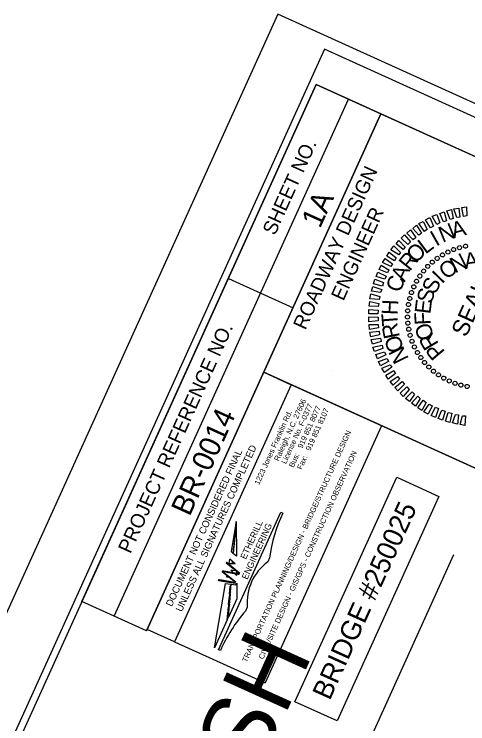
# Model space of a CAD drawing. Extents: x 1744741 to 2014229, y 466994 to 951338.
# Drawn here: x 2010827 to 2011187, y 477413 to 477976 of the extents above; entities that cross this region are included whole.
import ezdxf

# ---------------------------------------------------------------- set-up
doc = ezdxf.new("R2010")
doc.units = 0
for name, color, linetype in [('Old_Level_1', 7, 'Continuous'), ('Old_Level_30', 7, 'Continuous'), ('Old_Level_31', 7, 'Continuous'), ('Old_Level_34', 7, 'Continuous'), ('Old_Level_49', 7, 'Continuous'), ('Old_Level_50', 7, 'Continuous'), ('Prop Guardrail', 7, 'Continuous'), ('Sheet Data Field CELL', 7, 'Continuous'), ('Sheet Plan CELL', 7, 'Continuous'), ('Sheet Plot Border Inside CELL', 7, 'Continuous'), ('Sheet Plot Border Outside CELL', 7, 'Continuous'), ('Sheet Sticker Exception Certification CELL', 7, 'Continuous'), ('Sheet Sticker Preliminary CELL', 7, 'Continuous')]:
    doc.layers.add(name, color=color, linetype=linetype)

msp = doc.modelspace()

# ---------------------------------------------------------------- linework, layer by layer
at = {"layer": 'Old_Level_1'}
msp.add_line((2010603.58, 476285.44), (2011175.48, 477547.17), dxfattribs=at)
at = {"layer": 'Old_Level_30'}
for p, q in [((2011046.61, 477681.87), (2010954.24, 477478.1)), ((2011118.33, 477649.36), (2011046.61, 477681.87)), ((2011118.33, 477649.36), (2011025.97, 477445.59)), ((2010954.24, 477478.1), (2011025.97, 477445.59))]:
    msp.add_line(p, q, dxfattribs=at)
at = {"layer": 'Old_Level_34'}
msp.add_lwpolyline([(2011049.62, 477430.54), (2011130.29, 477608.53), (2011163.83, 477593.33), (2011083.15, 477415.34)], close=True, dxfattribs=at)
at = {"layer": 'Old_Level_49'}
for p, q in [((2010988.95, 477471.76), (2011038.41, 477580.88)), ((2011038.41, 477580.88), (2011039.97, 477580.17)), ((2011003.08, 477573.41), (2010999, 477549.69)), ((2011002.64, 477567.97), (2011002.84, 477570.47)), ((2011002.84, 477570.81), (2011002.8, 477570.38)), ((2011002.8, 477570.38), (2011002.84, 477570.47)), ((2011002.88, 477570.88), (2011002.84, 477570.81)), ((2011002.88, 477570.88), (2011003, 477572.41)), ((2011003, 477572.53), (2011003.08, 477573.41)), ((2011003.01, 477572.56), (2011003.08, 477573.41)), ((2011003.08, 477573.41), (2011003.27, 477545.97)), ((2011002.18, 477563.56), (2011002.1, 477562.74)), ((2011002.31, 477563.85), (2011002.18, 477563.56)), ((2011002.31, 477563.85), (2011002.59, 477567.28)), ((2011002.57, 477567.8), (2011002.5, 477567.09)), ((2011002.5, 477567.09), (2011002.59, 477567.28)), ((2011002.64, 477567.97), (2011002.57, 477567.8)), ((2011001.64, 477555.58), (2011002.25, 477563.06)), ((2011002.1, 477562.74), (2011002.25, 477563.06)), ((2011000.76, 477548.16), (2011001.29, 477553.9)), ((2011001.02, 477547.93), (2011001.55, 477554.48)), ((2011001.39, 477555.04), (2011001.29, 477553.9)), ((2011001.29, 477553.9), (2011001.55, 477554.48)), ((2011001.64, 477555.58), (2011001.39, 477555.04)), ((2010999, 477549.69), (2011000.76, 477548.16)), ((2011003.27, 477545.97), (2011001.02, 477547.93)), ((2011000.17, 477541.75), (2010997.95, 477543.59)), ((2011000.02, 477540.11), (2011000.17, 477541.75)), ((2011000.5, 477541.47), (2011000.39, 477540.09)), ((2011002.27, 477540), (2011000.5, 477541.47)), ((2011029.46, 477544.54), (2011028.04, 477541.42)), ((2010997.38, 477540.23), (2011000.02, 477540.11)), ((2011000.39, 477540.09), (2011002.27, 477540)), ((2010995.5, 477529.33), (2010995.76, 477530.83)), ((2010995.76, 477530.83), (2010997.55, 477528.95)), ((2010998.84, 477534.95), (2010999.54, 477534.89)), ((2010999.49, 477534.32), (2010998.84, 477534.95)), ((2010999.54, 477534.89), (2010999.49, 477534.32)), ((2011003.37, 477530.55), (2010999.89, 477533.93)), ((2010999.97, 477534.85), (2011003.35, 477534.55)), ((2011003.35, 477534.55), (2011003.37, 477530.55)), ((2010985.84, 477473.17), (2010994.63, 477524.29)), ((2010994.63, 477524.29), (2010999.07, 477523.72)), ((2010997.55, 477528.95), (2010995.5, 477529.33)), ((2011002.79, 477523.23), (2011003.42, 477524.59)), ((2011003.42, 477524.59), (2011003.5, 477512.14)), ((2010999.07, 477523.72), (2010998.37, 477522.17)), ((2010998.58, 477517.64), (2010999.07, 477523.72)), ((2010998.58, 477517.64), (2010999.07, 477523.72)), ((2010999.07, 477523.72), (2011002.79, 477523.23)), ((2010997.65, 477514.36), (2010998.46, 477516.14)), ((2010997.79, 477515.91), (2010997.65, 477514.36)), ((2010998.58, 477517.64), (2010997.79, 477515.91)), ((2010997.92, 477509.51), (2010998.46, 477516.14)), ((2010996.85, 477505.64), (2010997.77, 477507.67)), ((2010997.02, 477507.53), (2010996.85, 477505.64)), ((2011003.5, 477512.14), (2010996.97, 477497.72)), ((2010996.97, 477497.72), (2010997.77, 477507.67)), ((2010997.92, 477509.51), (2010997.02, 477507.53)), ((2011011.79, 477505.57), (2011010.38, 477502.45)), ((2010995.9, 477495.38), (2010985.84, 477473.17)), ((2010990.51, 477471.05), (2010988.95, 477471.76))]:
    msp.add_line(p, q, dxfattribs=at)
for centre, radius, start, end in [((2011147.4, 477529.1), 118.95, 154.5736, 172.5442), ((2011051.95, 477508.98), 40.3, 126.3806, 184.8539), ((2011103.21, 477421.73), 123.02, 138.9892, 156.3604)]:
    msp.add_arc(centre, radius, start, end, dxfattribs=at)
at = {"layer": 'Old_Level_50'}
for p, q in [((2011002.57, 477567.8), (2011002.8, 477570.38)), ((2011002.84, 477570.81), (2011002.99, 477572.38)), ((2011003, 477572.53), (2011002.99, 477572.38)), ((2011002.99, 477572.38), (2011003, 477572.41)), ((2011003.01, 477572.56), (2011003, 477572.53)), ((2011003.01, 477572.56), (2011003.08, 477573.41)), ((2011002.18, 477563.56), (2011002.5, 477567.09)), ((2011001.39, 477555.04), (2011002.1, 477562.74)), ((2011001.02, 477547.93), (2011000.76, 477548.16)), ((2010997.38, 477540.23), (2010997.95, 477543.59)), ((2011000.5, 477541.47), (2011000.17, 477541.75)), ((2011000.39, 477540.09), (2011000.02, 477540.11)), ((2010999.49, 477534.32), (2010999.89, 477533.93)), ((2010999.54, 477534.89), (2010999.97, 477534.85)), ((2010999.89, 477533.93), (2010999.97, 477534.85)), ((2010997.79, 477515.91), (2010998.37, 477522.17)), ((2010997.02, 477507.53), (2010997.65, 477514.36)), ((2010996.85, 477505.64), (2010997.77, 477507.67)), ((2010997.77, 477507.67), (2010996.85, 477505.64)), ((2010995.9, 477495.38), (2010996.85, 477505.64)), ((2010995.9, 477495.38), (2010996.97, 477497.72))]:
    msp.add_line(p, q, dxfattribs=at)
at = {"layer": 'Prop Guardrail'}
for p, q in [((2011175.44, 477789.07), (2011175.44, 477789.07)), ((2011180.11, 477790.66), (2011180.11, 477790.66)), ((2011184.8, 477791.75), (2011184.8, 477791.75)), ((2011166.59, 477784.81), (2011166.59, 477784.81)), ((2011170.88, 477787.19), (2011170.88, 477787.19)), ((2011158.55, 477779.07), (2011158.55, 477779.07)), ((2011162.41, 477782.13), (2011162.41, 477782.13)), ((2011151.67, 477772.06), (2011151.67, 477772.06)), ((2011154.85, 477775.8), (2011154.85, 477775.8)), ((2011148.65, 477768.12), (2011148.65, 477768.12)), ((2011146.04, 477763.99), (2011146.04, 477763.99)), ((2011141.95, 477754.97), (2011141.95, 477754.97)), ((2011143.79, 477759.57), (2011143.79, 477759.57)), ((2011140.57, 477750.29), (2011140.57, 477750.29)), ((2011139.59, 477745.42), (2011139.59, 477745.42)), ((2011138.87, 477740.56), (2011138.87, 477740.56)), ((2011138.86, 477735.62), (2011138.86, 477735.62)), ((2011139.1, 477730.7), (2011139.1, 477730.7)), ((2011139.84, 477725.79), (2011139.84, 477725.79)), ((2011140.88, 477721), (2011140.88, 477721)), ((2011142.47, 477716.32), (2011142.47, 477716.32)), ((2011144.35, 477711.76), (2011144.35, 477711.76)), ((2011146.63, 477707.52), (2011146.63, 477707.52)), ((2011149.41, 477703.3), (2011149.41, 477703.3)), ((2011152.37, 477699.48), (2011152.37, 477699.48)), ((2011079.26, 477692.97), (2011079.26, 477692.97)), ((2011155.68, 477695.88), (2011155.68, 477695.88)), ((2011159.38, 477692.6), (2011159.38, 477692.6)), ((2011163.47, 477689.63), (2011163.47, 477689.63)), ((2011167.5, 477687.07), (2011167.5, 477687.07)), ((2011171.91, 477684.82), (2011171.91, 477684.82)), ((2011176.51, 477682.98), (2011176.51, 477682.98)), ((2011181.3, 477681.55), (2011181.3, 477681.55)), ((2011186.02, 477680.52), (2011186.02, 477680.52))]:
    msp.add_line(p, q, dxfattribs=at)
for points in [[(2011183.31, 477815.15), (2011181.88, 477822.35), (2011185.63, 477822.99), (2011186.05, 477815.76)], [(2011162.15, 477808.81), (2011158.48, 477815.41), (2011162.05, 477816.76), (2011164.47, 477810.1)], [(2011167.31, 477810.92), (2011164.39, 477817.55), (2011167.96, 477818.9), (2011169.69, 477811.81)], [(2011172.67, 477812.93), (2011170.04, 477819.68), (2011173.73, 477820.73), (2011175.16, 477813.53)], [(2011178, 477814.35), (2011175.72, 477821.31), (2011179.68, 477821.86), (2011180.4, 477814.74)], [(2011152.29, 477803.4), (2011147.92, 477809.58), (2011151.18, 477811.31), (2011154.54, 477805.09)], [(2011157.06, 477806.3), (2011153.2, 477812.5), (2011156.5, 477814.33), (2011159.38, 477807.59)], [(2011147.77, 477800.51), (2011143.03, 477805.86), (2011146.11, 477808.3), (2011149.88, 477801.9)], [(2011139.19, 477793.03), (2011133.86, 477798.16), (2011136.44, 477800.58), (2011141.12, 477795.12)], [(2011143.38, 477796.81), (2011138.34, 477802.06), (2011141.22, 477804.59), (2011145.42, 477798.6)], [(2011135.46, 477789.16), (2011129.76, 477793.48), (2011132.02, 477796.28), (2011137.05, 477791.04)], [(2011132, 477784.8), (2011125.66, 477788.79), (2011128.06, 477791.9), (2011133.39, 477786.77)], [(2011128.61, 477780.04), (2011122.42, 477783.83), (2011124.36, 477787.03), (2011129.93, 477782.41)], [(2011125.56, 477775.49), (2011119.14, 477778.77), (2011121.08, 477781.97), (2011127.08, 477777.77)], [(2011123.03, 477770.46), (2011116.38, 477773.23), (2011117.91, 477776.61), (2011124.15, 477772.92)], [(2011120.8, 477765.54), (2011113.92, 477767.8), (2011115.45, 477771.18), (2011121.92, 477768)], [(2011119.1, 477760.14), (2011111.98, 477761.89), (2011113.1, 477765.45), (2011119.8, 477762.79)], [(2011117.48, 477754.95), (2011110.34, 477756.08), (2011111.46, 477759.65), (2011118.39, 477757.5)], [(2011116.48, 477749.47), (2011109.11, 477750.1), (2011109.87, 477753.95), (2011117.05, 477751.81)], [(2011115.69, 477743.9), (2011108.42, 477744.23), (2011109.04, 477747.78), (2011116.05, 477746.33)], [(2011115.3, 477738.15), (2011108.1, 477738.07), (2011108.22, 477741.6), (2011115.6, 477740.98)], [(2011115.51, 477732.62), (2011108.24, 477731.84), (2011108.25, 477735.66), (2011115.51, 477735.34)], [(2011115.97, 477727.1), (2011108.68, 477725.71), (2011108.48, 477729.63), (2011115.63, 477729.6)], [(2011116.64, 477721.48), (2011109.75, 477719.91), (2011108.91, 477723.5), (2011116.43, 477724.29)], [(2011117.95, 477716.2), (2011110.99, 477713.92), (2011110.19, 477717.61), (2011117.4, 477718.79)], [(2011119.42, 477710.71), (2011112.82, 477708.15), (2011111.48, 477711.72), (2011118.87, 477713.31)], [(2011121.57, 477705.66), (2011115.11, 477702.29), (2011113.76, 477705.87), (2011120.68, 477708.04)], [(2011123.89, 477700.41), (2011117.53, 477696.75), (2011115.89, 477700.21), (2011122.7, 477702.68)], [(2011126.44, 477695.67), (2011120.6, 477691.53), (2011118.41, 477694.87), (2011125.15, 477697.74)], [(2011129.39, 477690.75), (2011123.67, 477686.31), (2011121.68, 477689.55), (2011128.04, 477693.22)], [(2011132.58, 477686.34), (2011127.48, 477681.62), (2011125.05, 477684.44), (2011131.29, 477688.41)], [(2011136.41, 477682.26), (2011131.28, 477676.93), (2011128.86, 477679.76), (2011134.62, 477684.31)], [(2011140.24, 477678.18), (2011135.52, 477672.66), (2011133, 477675.28), (2011138.45, 477680.22)], [(2011144.51, 477674.51), (2011140.36, 477668.61), (2011137.2, 477670.91), (2011142.58, 477676.25)], [(2011148.87, 477671.05), (2011145.13, 477664.97), (2011141.97, 477667.27), (2011146.94, 477672.79)], [(2011153.62, 477667.91), (2011150.24, 477661.54), (2011146.94, 477663.53), (2011151.4, 477669.54)], [(2011158.36, 477665.27), (2011155.34, 477658.61), (2011151.95, 477660.4), (2011155.99, 477666.59)], [(2011163.48, 477662.95), (2011161.08, 477656.01), (2011157.59, 477657.59), (2011161.02, 477664.06)], [(2011168.7, 477660.83), (2011166.7, 477653.71), (2011163.13, 477655.08), (2011166.14, 477661.74)], [(2011173.94, 477659.32), (2011172.56, 477651.92), (2011168.89, 477653.09), (2011171.25, 477659.92)], [(2011179.32, 477658.12), (2011178.45, 477650.73), (2011174.64, 477651.59), (2011176.95, 477658.33)], [(2011184.8, 477657.12), (2011184.33, 477649.55), (2011180.73, 477650.32), (2011182.42, 477657.33)]]:
    msp.add_lwpolyline(points, close=True, dxfattribs=at)
for centre, major_axis in [((2011170.88, 477787.08), (-0.7, 1.46)), ((2011175.4, 477789.02), (-0.57, 1.52)), ((2011180.08, 477790.55), (-0.44, 1.56)), ((2011184.88, 477791.67), (-0.3, 1.59)), ((2011162.41, 477782.07), (-0.94, 1.32)), ((2011166.53, 477784.76), (-0.83, 1.39)), ((2011154.94, 477775.67), (-1.16, 1.13)), ((2011158.54, 477779.04), (-1.05, 1.23)), ((2011151.66, 477772.01), (-1.25, 1.03)), ((2011148.7, 477768.07), (-1.34, 0.91)), ((2011143.88, 477759.5), (-1.48, 0.67)), ((2011146.1, 477763.89), (-1.41, 0.79)), ((2011142.04, 477754.93), (-1.53, 0.54)), ((2011140.61, 477750.22), (-1.57, 0.4)), ((2011139.6, 477745.4), (-1.6, 0.26)), ((2011139.01, 477740.51), (-1.62, 0.12)), ((2011138.85, 477735.59), (-1.62, -0.02)), ((2011139.12, 477730.68), (-1.61, -0.16)), ((2011139.81, 477725.8), (-1.59, -0.3)), ((2011140.93, 477721.01), (-1.56, -0.44)), ((2011142.46, 477716.33), (-1.52, -0.57)), ((2011144.39, 477711.8), (-1.46, -0.7)), ((2011146.71, 477707.46), (-1.39, -0.83)), ((2011149.4, 477703.34), (-1.32, -0.94)), ((2011152.44, 477699.47), (-1.23, -1.05)), ((2011155.8, 477695.87), (-1.13, -1.16)), ((2011159.47, 477692.59), (-1.03, -1.25)), ((2011163.41, 477689.63), (-0.91, -1.34)), ((2011167.59, 477687.03), (-0.79, -1.41)), ((2011171.98, 477684.8), (-0.67, -1.48)), ((2011176.55, 477682.97), (-0.54, -1.53)), ((2011181.26, 477681.54), (-0.4, -1.57)), ((2011186.07, 477680.53), (-0.26, -1.6))]:
    msp.add_ellipse(centre, major_axis=major_axis, ratio=0.999708, dxfattribs=at)
at = {"layer": 'Sheet Plan CELL'}
for p, q in [((2010906.4, 477498.27), (2011092.22, 477908.24)), ((2010932.02, 477486.66), (2011117.84, 477896.63)), ((2010932.02, 477486.66), (2011117.84, 477896.63)), ((2010996.94, 477766.15), (2011048.17, 477742.93)), ((2011024.95, 477691.7), (2011255.4, 477587.24))]:
    msp.add_line(p, q, dxfattribs=at)
for points in [[(2011066.5, 477919.9), (2009673.19, 474845.92), (2011824.97, 473870.61), (2013218.28, 476944.58)], [(2010880.68, 477509.93), (2011066.5, 477919.9), (2011117.84, 477896.63), (2010932.02, 477486.66)], [(2011024.95, 477691.7), (2011117.84, 477896.63), (2011348.39, 477792.13), (2011255.5, 477587.2)]]:
    msp.add_lwpolyline(points, close=True, dxfattribs=at)
at = {"layer": 'Sheet Plot Border Inside CELL'}
msp.add_lwpolyline([(2011687.52, 473553.71), (2013235.02, 476967.87), (2011072.99, 477947.84), (2009525.49, 474533.68)], close=True, dxfattribs=at)
at = {"layer": 'Sheet Plot Border Outside CELL'}
msp.add_lwpolyline([(2011716.43, 473508.5), (2013280.18, 476958.52), (2011036.18, 477975.63), (2009472.43, 474525.61)], close=True, dxfattribs=at)
at = {"layer": 'Sheet Sticker Exception Certification CELL'}
for p, q in [((2010932.57, 477487.92), (2011024.94, 477691.7)), ((2011024.95, 477691.7), (2011046.62, 477681.87)), ((2011046.61, 477681.88), (2010954.24, 477478.1)), ((2010954.24, 477478.1), (2010932.57, 477487.92))]:
    msp.add_line(p, q, dxfattribs=at)

# ---------------------------------------------------------------- texts
at = {"layer": 'Old_Level_1'}
msp.add_text('BRIDGE #250025', height=15.7275, rotation=65.6171, dxfattribs=at).set_placement((2011077.18, 477430.96))
at = {"layer": 'Old_Level_31'}
for s, height, p in [('Raleigh, N.C. 27606', 4.2787, (2011036.75, 477620.93)), ('License No. F-0377', 4.2787, (2011042.58, 477618.67)), ('Bus:   919 851 8077', 4.2787, (2011048.49, 477615.78)), ('Fax:   919 851 8107', 4.2787, (2011055, 477614.2)), ('     1223 Jones Franklin Rd. ', 4.2787, (2011017.74, 477594.62)), ('ETHERILL', 5.134, (2011010.75, 477542.98)), ('ENGINEERING', 5.1344, (2011011.86, 477526.93)), ('W', 13.69, (2011000.67, 477520.54))]:
    msp.add_text(s, height=height, rotation=65.6171, dxfattribs=at).set_placement(p)
at = {"layer": 'Old_Level_50'}
for s, p in [('TRANSPORTATION PLANNING/DESIGN - BRIDGE/STRUCTURE DESIGN', (2011011.4, 477461.46)), ('CIVIL/SITE DESIGN - GIS/GPS - CONSTRUCTION OBSERVATION', (2011024.43, 477463.8))]:
    msp.add_text(s, height=4.2787, rotation=65.6171, dxfattribs=at).set_placement(p)
at = {"layer": 'Prop Guardrail'}
for s, height, rotation, p in [('A', 12.69, 15.2343, (2011175.41, 477797.73)), ('N', 12.69, 22.436, (2011166.68, 477794.28)), ('I', 12.68, 29.6373, (2011161.61, 477791.27)), ('L', 12.69, 36.838, (2011153.09, 477785)), ('O', 12.69, 44.0383, (2011145.27, 477777.55)), ('R', 12.69, 51.2382, (2011140.72, 477771.34)), ('N', 12.69, 27.0937, (2011176.62, 477769.89)), ('A', 12.69, 8.3774, (2011184.65, 477773.41)), ('O', 12.69, 36.4506, (2011169.62, 477764.79)), ('A', 12.68, 65.6374, (2011136.62, 477762.82)), ('I', 12.69, 45.8067, (2011166.28, 477761.24)), ('C', 12.68, 72.837, (2011133.56, 477754.45)), ('S', 12.68, 64.5175, (2011161.06, 477752.98)), ('SEAL', 13.496, 65.6171, (2011185.37, 477718.86)), ('S', 12.68, 73.8727, (2011157.92, 477745.51)), ('E', 12.69, 83.2282, (2011157.01, 477737.52)), ('H', 12.69, 87.2366, (2011131.06, 477736.93)), ('T', 12.69, 94.4369, (2011131.52, 477728.7)), ('F', 12.69, 92.5841, (2011157.32, 477729.48)), ('R', 12.69, 101.6376, (2011132.92, 477719.79)), ('O', 12.69, 111.2984, (2011160.45, 477720.03)), ('R', 12.69, 120.6568, (2011163.99, 477714.22)), ('O', 12.69, 108.8389, (2011136.32, 477709.85)), ('N', 12.69, 116.0406, (2011140.17, 477702.54)), ('P', 12.69, 130.016, (2011169.11, 477708.08))]:
    msp.add_text(s, height=height, rotation=rotation, dxfattribs=at).set_placement(p)
at = {"layer": 'Sheet Data Field CELL'}
for s, p in [('1A ', (2011069.48, 477805.19)), ('BR-0014', (2010966.12, 477576.88))]:
    msp.add_text(s, height=16.875, rotation=65.6171, dxfattribs=at).set_placement(p)
at = {"layer": 'Sheet Plan CELL'}
for s, height, p in [('SHEET NO.', 11.25, (2011033.73, 477799.62)), ('ROADWAY DESIGN', 11.2502, (2011057.93, 477724.67)), ('ENGINEER', 11.25, (2011088.02, 477747.72)), ('PROJECT REFERENCE NO.', 11.2502, (2010919.13, 477547.34))]:
    msp.add_text(s, height=height, rotation=65.6171, dxfattribs=at).set_placement(p)
at = {"layer": 'Sheet Sticker Exception Certification CELL'}
for s, p in [('UNLESS ALL SIGNATURES COMPLETED', (2010959.95, 477501.36)), ('DOCUMENT NOT CONSIDERED FINAL', (2010952.05, 477505.51))]:
    msp.add_text(s, height=5.5687, rotation=65.6171, dxfattribs=at).set_placement(p)
at = {"layer": 'Sheet Sticker Preliminary CELL'}
msp.add_text('2018 ROADWAY ENGLISH ', height=56.2498, rotation=65.6171, dxfattribs=at).set_placement((2010680.68, 476622.85))

doc.saveas('drawing.dxf')
